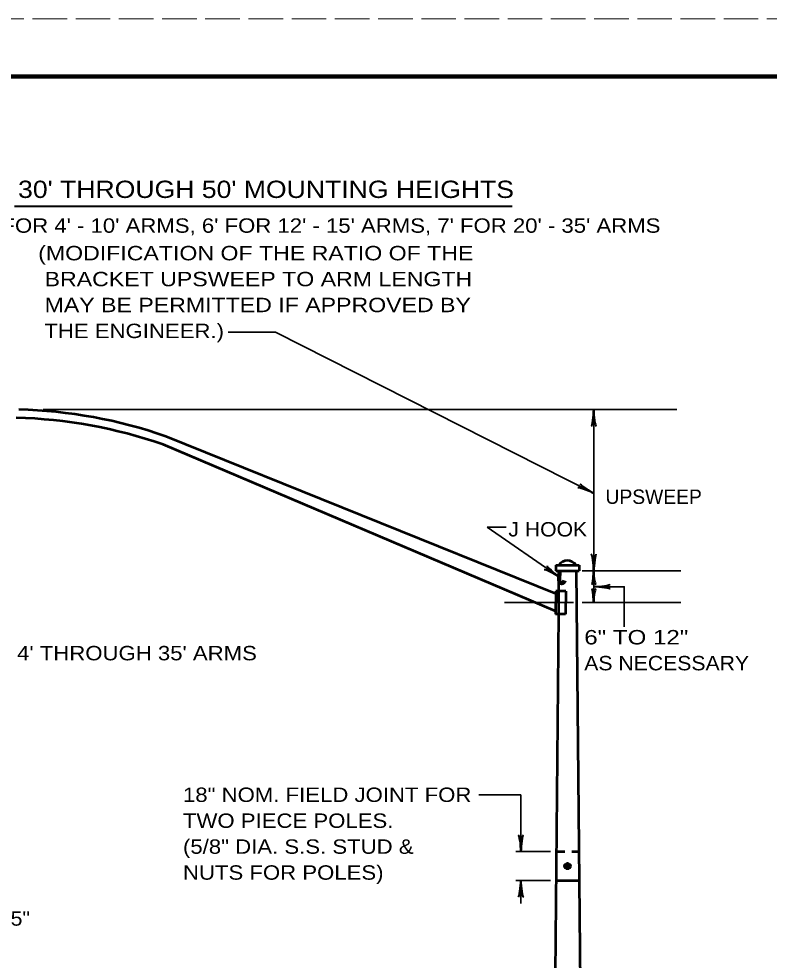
# Model space of a CAD drawing. Extents: x -1 to 679, y -228 to 440.
# Drawn here: x 94.1 to 224.4, y 276.8 to 440.2 of the extents above; entities that cross this region are included whole.
import ezdxf
from ezdxf.enums import TextEntityAlignment as Align

# ---------------------------------------------------------------- set-up
doc = ezdxf.new("R2010")
doc.units = 0
doc.linetypes.add('LONG_DASHED', pattern=[7.5, 6, -1.5])
doc.linetypes.add('SHORT_DASHED', pattern=[2.7, 1.5, -1.2])
doc.layers.add('1', color=7, linetype='Continuous', lineweight=35)
doc.layers.add('61', color=7, linetype='Continuous', lineweight=35)

msp = doc.modelspace()

# ---------------------------------------------------------------- hatches: boundary and pattern name
at = {"layer": '1'}
msp.add_hatch(color=256, dxfattribs=at).paths.add_polyline_path([(189.888, 293.165, 1), (188.888, 293.165, 1)])

# ---------------------------------------------------------------- linework, layer by layer
at = {"layer": '1', "lineweight": 40}
msp.add_line((93.409, 407.69), (179.76, 407.69), dxfattribs=at)
at = {"layer": '1'}
for p, q in [((98.393, 372.411), (208.393, 372.411)), ((193.945, 344.411), (193.945, 372.411)), ((175.442, 351.987), (178.75, 351.987)), ((175.442, 351.987), (187.982, 343.297)), ((191.945, 344.411), (209.091, 344.411)), ((193.945, 344.411), (193.945, 338.911)), ((178.445, 338.911), (190.445, 338.911)), ((191.945, 338.911), (209.091, 338.911)), ((181.298, 305.522), (174.004, 305.522)), ((181.298, 295.661), (181.298, 305.522)), ((186.436, 295.661), (180.436, 295.661)), ((186.436, 290.661), (180.436, 290.661)), ((181.298, 286.661), (181.298, 290.661))]:
    msp.add_line(p, q, dxfattribs=at)
at = {"layer": '1', "lineweight": 53}
for p, q in [((187.36, 340.411), (119.676, 367.757)), ((187.323, 337.411), (119.205, 366.325)), ((187.393, 345.411), (191.393, 345.411)), ((187.393, 345.411), (187.393, 344.411)), ((191.393, 345.411), (191.393, 344.411)), ((187.393, 344.411), (191.393, 344.411)), ((190.893, 344.411), (191.784, 249.412)), ((187.36, 340.911), (187.323, 336.911)), ((189.11, 340.911), (187.36, 340.911)), ((189.11, 340.911), (189.073, 336.911)), ((189.073, 336.911), (187.323, 336.911)), ((187.389, 290.661), (191.397, 290.661))]:
    msp.add_line(p, q, dxfattribs=at)
at = {"layer": '1', "lineweight": 90}
msp.add_line((187.993, 344.411), (187.976, 342.661), dxfattribs=at)
at = {"layer": '1', "linetype": 'SHORT_DASHED', "lineweight": 53}
msp.add_line((187.436, 295.661), (191.35, 295.661), dxfattribs=at)
at = {"layer": '1'}
for points in [[(193.935, 357.878), (138.687, 385.856), (130.502, 385.856)], [(193.945, 341.661), (199.26, 341.661), (199.26, 334.69)]]:
    msp.add_lwpolyline(points, dxfattribs=at)
at = {"layer": '1', "lineweight": 53}
msp.add_lwpolyline([(187.893, 344.411), (187.86, 340.911), (187.823, 336.911), (187.002, 249.412)], dxfattribs=at)
msp.add_circle((189.388, 293.165), 0.5, dxfattribs=at)
for centre, radius, start, end in [((91.455, 286.443), 84.565, 70.84342, 88.49759), ((91.926, 287.875), 84.565, 70.84342, 88.49759), ((189.393, 344.363), 1.822, 35.09936, 144.90064)]:
    msp.add_arc(centre, radius, start, end, dxfattribs=at)
at = {"layer": '1', "lineweight": 90}
msp.add_arc((188.415, 342.719), 0.442, 187.53327, 0.04815, dxfattribs=at)
at = {"layer": '1', "lineweight": 40}
for centre, major_axis, ratio, start_param, end_param in [((193.733, 371.29), (0.176, 1.756), 0.07063, 3.1407148, 5.41811), ((194.221, 371.32), (-0.156, 1.786), 0.122415, 0.8963533, 3.1415927), ((193.031, 358.573), (-1.488, 0.95), 0.07063, 6.2823074, 8.5597026), ((192.836, 358.125), (1.664, -0.667), 0.122415, 0.8963533, 3.1415927), ((193.668, 345.502), (0.156, -1.786), 0.122415, 0.8963533, 3.1415927), ((194.156, 345.531), (-0.176, -1.756), 0.07063, 3.1407148, 5.41811), ((187.182, 344.109), (-1.344, 1.145), 0.07063, 6.2823074, 8.5597026), ((186.928, 343.691), (1.557, -0.889), 0.122415, 0.8963533, 3.1415927), ((193.736, 343.281), (0.176, 1.756), 0.07063, 4.6265008, 5.41811), ((194.224, 343.31), (-0.156, 1.786), 0.122415, 0.8963533, 1.6612166), ((193.794, 343.773), (0.176, 1.756), 0.07063, 3.1407148, 4.3375003), ((195.065, 341.449), (-1.756, 0.176), 0.07063, 3.1407148, 5.41811), ((195.036, 341.937), (-1.786, -0.156), 0.122415, 0.8963533, 3.1415927), ((194.164, 343.82), (-0.156, 1.786), 0.122415, 1.9568509, 3.1415927), ((193.794, 339.549), (0.176, -1.756), 0.07063, 1.9456851, 3.1424706), ((193.736, 340.041), (0.176, -1.756), 0.07063, 0.8650754, 1.6566845), ((194.224, 340.011), (-0.156, -1.786), 0.122415, 4.6219687, 5.386832), ((194.164, 339.502), (-0.156, -1.786), 0.122415, 3.1415927, 4.3263344), ((181.021, 296.752), (0.156, -1.786), 0.122415, 0.8963533, 3.1415927), ((181.021, 296.752), (0.156, -1.786), 0.122415, 0.8963533, 3.1415927), ((181.509, 296.782), (-0.176, -1.756), 0.07063, 3.1407148, 5.41811), ((181.509, 296.782), (-0.176, -1.756), 0.07063, 3.1407148, 5.41811), ((181.086, 289.541), (0.176, 1.756), 0.07063, 3.1407148, 5.41811), ((181.086, 289.541), (0.176, 1.756), 0.07063, 3.1407148, 5.41811), ((181.574, 289.57), (-0.156, 1.786), 0.122415, 0.8963533, 3.1415927), ((181.574, 289.57), (-0.156, 1.786), 0.122415, 0.8963533, 3.1415927)]:
    msp.add_ellipse(centre, major_axis=major_axis, ratio=ratio, start_param=start_param, end_param=end_param, dxfattribs=at)
at = {"layer": '61', "linetype": 'LONG_DASHED', "lineweight": 13}
msp.add_line((-0.979, 440.237), (679.041, 440.237), dxfattribs=at)
at = {"layer": '61', "lineweight": 158}
msp.add_lwpolyline([(668.061, 430.237), (29.021, 430.237), (29.021, 10.217)], dxfattribs=at)

# ---------------------------------------------------------------- texts
at = {"layer": '1'}
for s, height, width, p in [("30' THROUGH 50' MOUNTING HEIGHTS", 3, 1.15, (94.011, 409.141)), ('(MODIFICATION OF THE RATIO OF THE', 2.5, 1.2, (97.505, 398.314)), (' BRACKET UPSWEEP TO ARM LENGTH', 2.5, 1.2, (97.505, 393.814)), (' MAY BE PERMITTED IF APPROVED BY', 2.5, 1.2, (97.505, 389.314)), (' THE ENGINEER.)', 2.5, 1.15, (97.505, 384.814)), ('J HOOK', 2.5, 1.1, (179.125, 350.373)), ('6" TO 12"', 2.5, 1.25, (192.305, 331.638)), ("4' THROUGH 35' ARMS", 2.5, 1.15, (93.841, 328.877)), ('AS NECESSARY', 2.5, 1.1, (192.305, 327.138)), ('18" NOM. FIELD JOINT FOR', 2.5, 1.15, (122.639, 304.291)), ('TWO PIECE POLES.', 2.5, 1.15, (122.639, 299.791)), ('(5/8" DIA. S.S. STUD &', 2.5, 1.15, (122.639, 295.291)), ('NUTS FOR POLES)', 2.5, 1.15, (122.639, 290.791)), ('10 GA.   0.1345"', 2.5, 1.1, (69.01, 282.813))]:
    msp.add_text(s, height=height, dxfattribs=dict(at, width=width)).set_placement(p)
at = {"layer": '1', "width": 1.15}
msp.add_text("UPSWEEP 3' FOR 4' - 10' ARMS, 6' FOR 12' - 15' ARMS, 7' FOR 20' - 35' ARMS", height=2.5, dxfattribs=at).set_placement((136.21, 403.097), align=Align.CENTER)
at = {"layer": '1'}
msp.add_text('UPSWEEP', height=2.5, dxfattribs=at).set_placement((195.995, 356.03))

doc.saveas('drawing.dxf')
